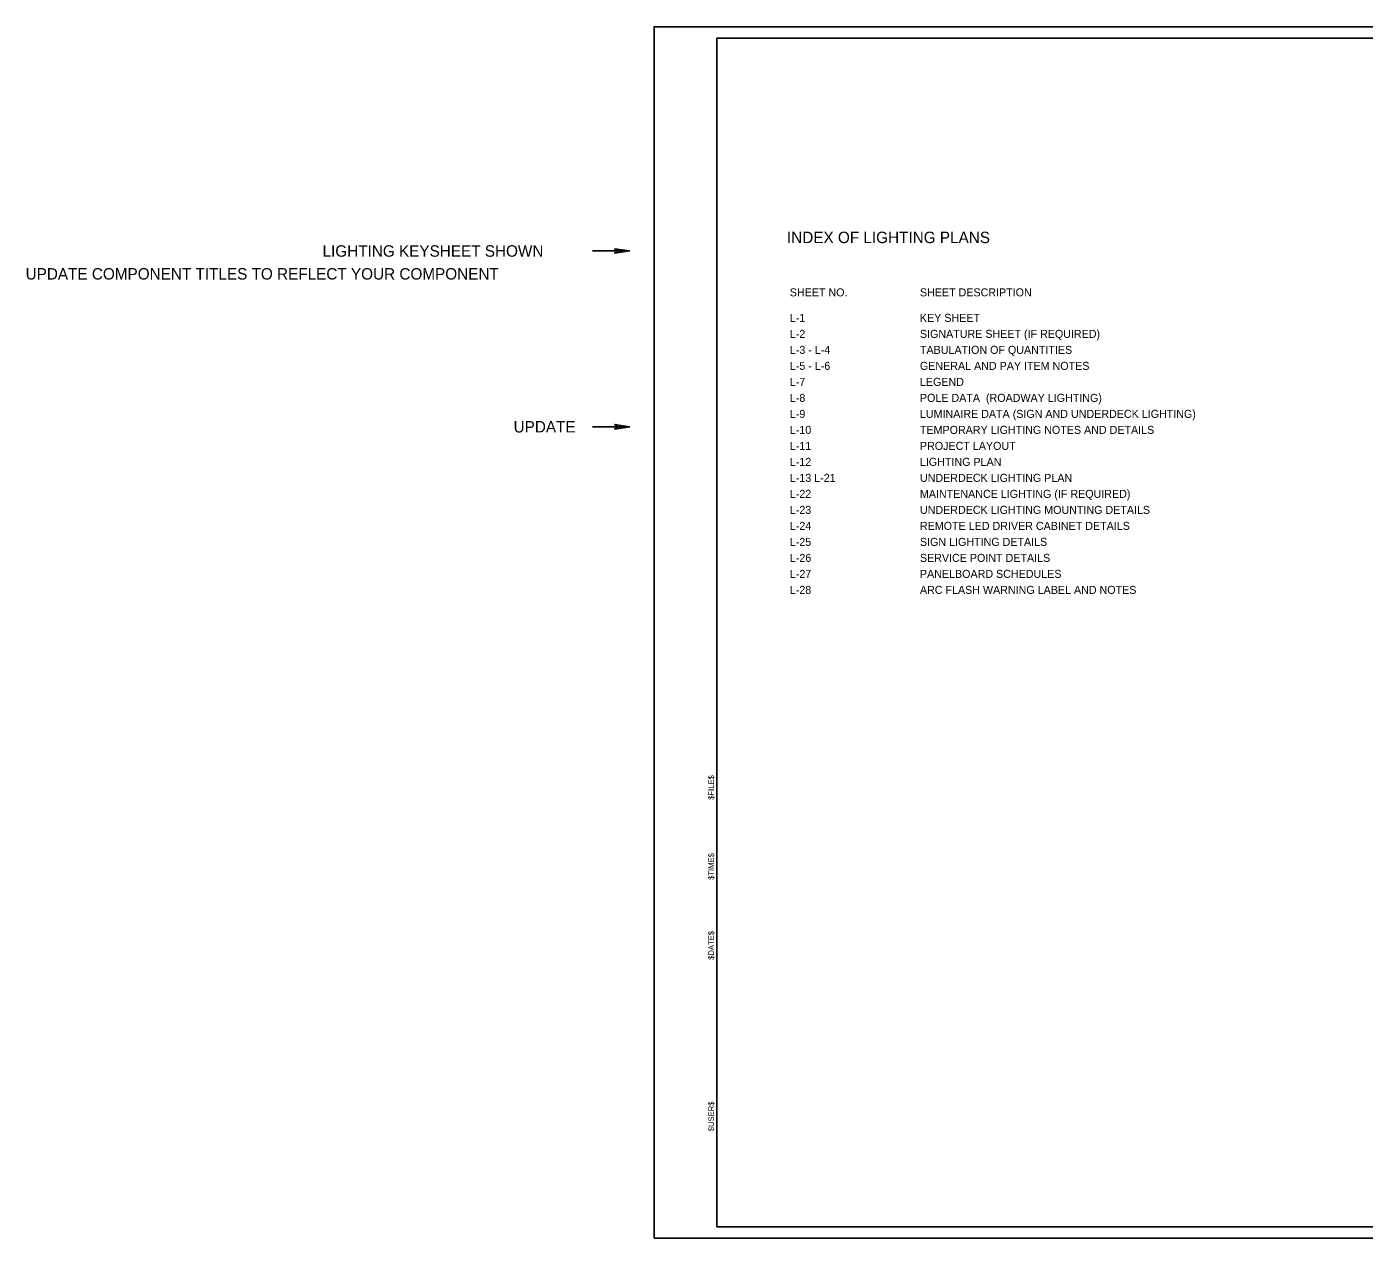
# Model space of a CAD drawing. Extents: x -830013.9 to -829988.1, y 1290300 to 1290310.6.
# Drawn here: x -830013.86 to -830002.16, y 1290299.98 to 1290310.58 of the extents above; entities that cross this region are included whole.
import ezdxf

# ---------------------------------------------------------------- set-up
doc = ezdxf.new("R2010")
doc.units = 0
for name, color, linetype in [('NonPlottingEle_dp', 7, 'Continuous'), ('PlotBorder_dp', 7, 'Continuous'), ('SheetBorder_dp', 7, 'Continuous'), ('TextLabel', 7, 'Continuous'), ('TextMinor', 7, 'Continuous'), ('TextNotes', 7, 'Continuous')]:
    doc.layers.add(name, color=color, linetype=linetype)

msp = doc.modelspace()

# ---------------------------------------------------------------- linework, layer by layer
at = {"layer": 'NonPlottingEle_dp'}
for p, q in [((-830008.912, 1290308.616), (-830008.587, 1290308.616)), ((-830008.693, 1290308.616), (-830008.719, 1290308.636)), ((-830008.719, 1290308.636), (-830008.587, 1290308.616)), ((-830008.587, 1290308.616), (-830008.719, 1290308.596)), ((-830008.719, 1290308.596), (-830008.693, 1290308.616)), ((-830008.693, 1290307.078), (-830008.719, 1290307.098)), ((-830008.719, 1290307.098), (-830008.587, 1290307.078)), ((-830008.912, 1290307.078), (-830008.587, 1290307.078)), ((-830008.587, 1290307.078), (-830008.719, 1290307.058)), ((-830008.719, 1290307.058), (-830008.693, 1290307.078))]:
    msp.add_line(p, q, dxfattribs=at)
at = {"layer": 'PlotBorder_dp'}
msp.add_lwpolyline([(-830008.374, 1290299.978), (-829991.874, 1290299.978), (-829991.874, 1290310.578), (-830008.374, 1290310.578)], close=True, dxfattribs=at)
at = {"layer": 'SheetBorder_dp'}
for p, q in [((-830007.824, 1290310.478), (-830007.824, 1290300.078)), ((-830007.824, 1290310.478), (-829992.424, 1290310.478)), ((-830007.824, 1290300.078), (-829992.424, 1290300.078))]:
    msp.add_line(p, q, dxfattribs=at)

# ---------------------------------------------------------------- texts
at = {"layer": 'NonPlottingEle_dp'}
for s, p in [('LIGHTING KEYSHEET SHOWN', (-830011.274, 1290308.566)), ('UPDATE COMPONENT TITLES TO REFLECT YOUR COMPONENT', (-830013.871, 1290308.366)), ('UPDATE', (-830009.603, 1290307.028))]:
    msp.add_text(s, height=0.1, dxfattribs=at).set_placement(p)
at = {"layer": 'TextLabel'}
msp.add_text('INDEX OF LIGHTING PLANS', height=0.1, dxfattribs=at).set_placement((-830007.212, 1290308.685))
at = {"layer": 'TextMinor'}
for s, p in [('$FILE$', (-830007.85, 1290303.814)), ('$TIME$', (-830007.85, 1290303.114)), ('$DATE$', (-830007.85, 1290302.414)), ('$USER$', (-830007.85, 1290300.914))]:
    msp.add_text(s, height=0.05, rotation=90, dxfattribs=at).set_placement(p)
at = {"layer": 'TextNotes'}
for s, p in [('SHEET NO.', (-830007.187, 1290308.219)), ('SHEET DESCRIPTION', (-830006.049, 1290308.219)), ('L-1', (-830007.187, 1290307.996)), ('KEY SHEET', (-830006.049, 1290307.996)), ('L-2 ', (-830007.187, 1290307.856)), ('SIGNATURE SHEET (IF REQUIRED)', (-830006.049, 1290307.856)), ('L-3 - L-4', (-830007.187, 1290307.716)), ('TABULATION OF QUANTITIES', (-830006.049, 1290307.716)), ('L-5 - L-6', (-830007.187, 1290307.576)), ('GENERAL AND PAY ITEM NOTES', (-830006.049, 1290307.576)), ('L-7 ', (-830007.187, 1290307.436)), ('LEGEND', (-830006.049, 1290307.436)), ('L-8', (-830007.187, 1290307.296)), ('POLE DATA  (ROADWAY LIGHTING)', (-830006.049, 1290307.296)), ('L-9', (-830007.187, 1290307.156)), ('LUMINAIRE DATA (SIGN AND UNDERDECK LIGHTING)', (-830006.049, 1290307.156)), ('L-10', (-830007.187, 1290307.016)), ('TEMPORARY LIGHTING NOTES AND DETAILS', (-830006.049, 1290307.016)), ('L-11', (-830007.187, 1290306.876)), ('PROJECT LAYOUT', (-830006.049, 1290306.876)), ('L-12', (-830007.187, 1290306.736)), ('LIGHTING PLAN', (-830006.049, 1290306.736)), ('L-13 L-21', (-830007.187, 1290306.596)), ('UNDERDECK LIGHTING PLAN', (-830006.049, 1290306.596)), ('L-22', (-830007.187, 1290306.456)), ('MAINTENANCE LIGHTING (IF REQUIRED)', (-830006.049, 1290306.456)), ('L-23', (-830007.187, 1290306.316)), ('UNDERDECK LIGHTING MOUNTING DETAILS', (-830006.049, 1290306.316)), ('L-24', (-830007.187, 1290306.176)), ('REMOTE LED DRIVER CABINET DETAILS', (-830006.049, 1290306.176)), ('L-25', (-830007.187, 1290306.036)), ('SIGN LIGHTING DETAILS', (-830006.049, 1290306.036)), ('L-26', (-830007.187, 1290305.896)), ('SERVICE POINT DETAILS', (-830006.049, 1290305.896)), ('L-27', (-830007.187, 1290305.756)), ('PANELBOARD SCHEDULES', (-830006.049, 1290305.756)), ('L-28', (-830007.187, 1290305.616)), ('ARC FLASH WARNING LABEL AND NOTES', (-830006.049, 1290305.616))]:
    msp.add_text(s, height=0.07, dxfattribs=at).set_placement(p)

doc.saveas('drawing.dxf')
